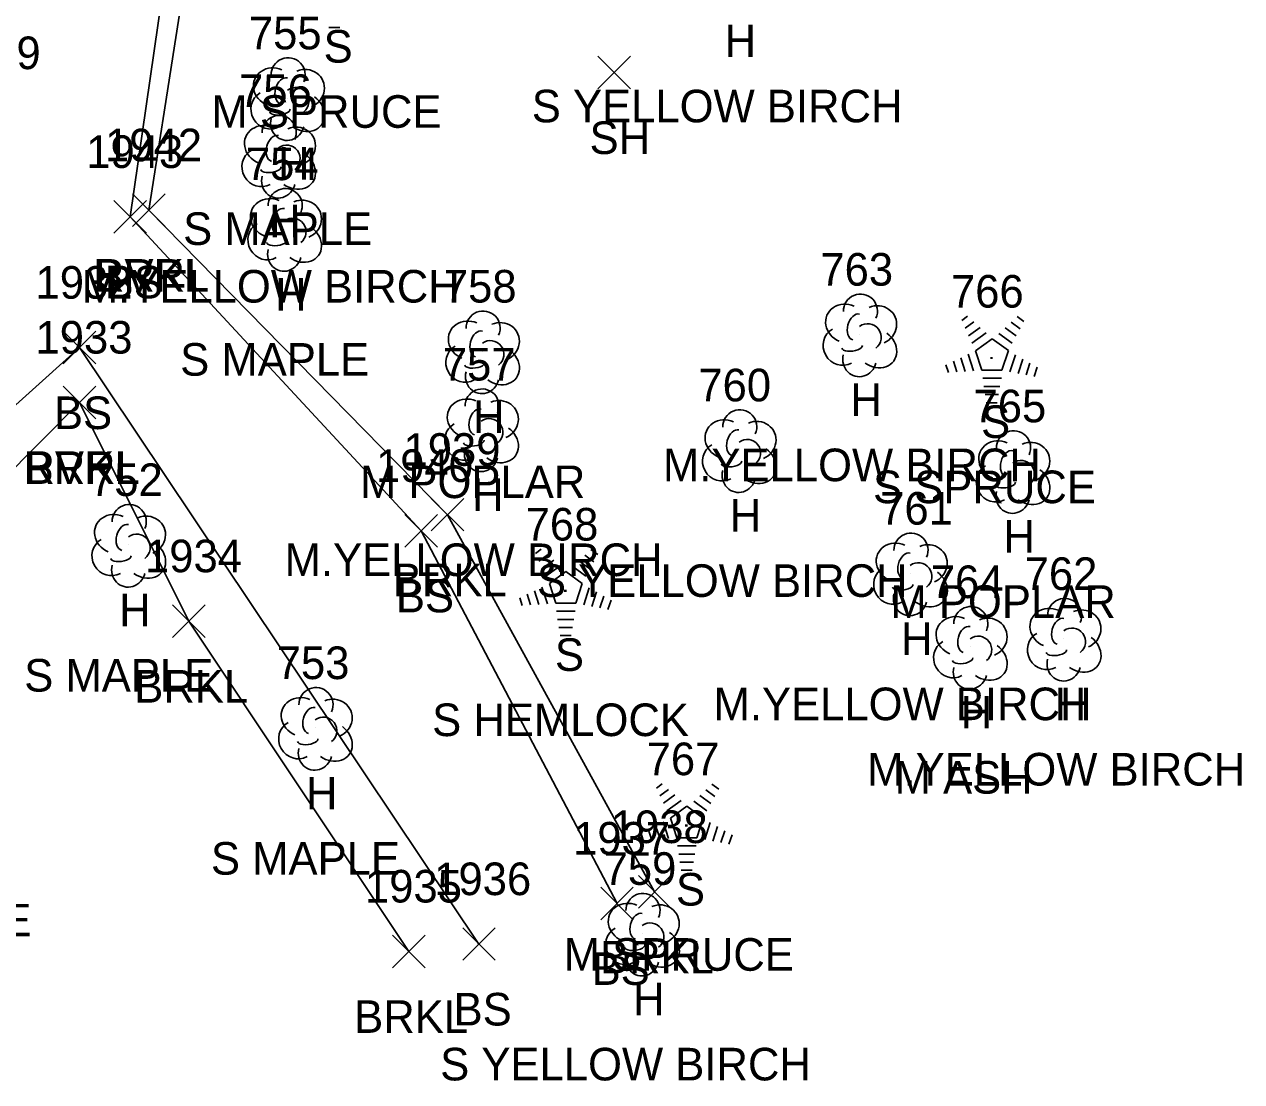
# Model space of a CAD drawing. Extents: x 1545627 to 1546562, y 571176 to 576667.
# Drawn here: x 1546286.7 to 1546361.4, y 572282.6 to 572347.5 of the extents above; entities that cross this region are included whole.
import ezdxf

# ---------------------------------------------------------------- set-up
doc = ezdxf.new("R2010")
doc.units = 0
for name, color, linetype in [('L_A', 7, 'Continuous'), ('L_C', 7, 'Continuous'), ('L_I', 7, 'Continuous'), ('L_TIC', 7, 'Continuous'), ('LAWE', 7, 'Continuous'), ('LELB', 7, 'Continuous'), ('LTC', 7, 'Continuous'), ('LTD', 7, 'Continuous')]:
    doc.layers.add(name, color=color, linetype=linetype)

msp = doc.modelspace()

# ---------------------------------------------------------------- linework, layer by layer
at = {"layer": 'L_TIC'}
for points in [[(1546321.87, 572343.496), (1546323.87, 572345.496)], [(1546323.87, 572343.496), (1546321.87, 572345.496)], [(1546292.177, 572334.64), (1546294.177, 572336.64)], [(1546294.177, 572334.64), (1546292.177, 572336.64)], [(1546293.332, 572335.048), (1546295.332, 572337.048)], [(1546295.332, 572335.048), (1546293.332, 572337.048)], [(1546293.332, 572335.048), (1546295.332, 572337.048)], [(1546295.332, 572335.048), (1546293.332, 572337.048)], [(1546289.068, 572326.618), (1546291.068, 572328.618)], [(1546291.068, 572326.618), (1546289.068, 572328.618)], [(1546289.065, 572323.25), (1546291.065, 572325.25)], [(1546291.065, 572323.25), (1546289.065, 572325.25)], [(1546289.065, 572323.25), (1546291.065, 572325.25)], [(1546291.065, 572323.25), (1546289.065, 572325.25)], [(1546311.645, 572316.364), (1546313.645, 572318.364)], [(1546313.645, 572316.364), (1546311.645, 572318.364)], [(1546310.037, 572315.372), (1546312.037, 572317.372)], [(1546312.037, 572315.372), (1546310.037, 572317.372)], [(1546295.785, 572309.832), (1546297.785, 572311.832)], [(1546297.785, 572309.832), (1546295.785, 572311.832)], [(1546324.351, 572293.214), (1546326.351, 572295.214)], [(1546326.351, 572293.214), (1546324.351, 572295.214)], [(1546322.042, 572292.51), (1546324.042, 572294.51)], [(1546324.042, 572292.51), (1546322.042, 572294.51)], [(1546313.576, 572290.02), (1546315.576, 572292.02)], [(1546315.576, 572290.02), (1546313.576, 572292.02)], [(1546309.275, 572289.567), (1546311.275, 572291.567)], [(1546311.275, 572289.567), (1546309.275, 572291.567)]]:
    msp.add_lwpolyline(points, dxfattribs=at)
at = {"layer": 'LAWE'}
for points in [[(1546294.332, 572336.048), (1546297.64, 572357.253), (1546293.462, 572395.876)], [(1546325.351, 572294.214), (1546312.645, 572317.364), (1546294.332, 572336.048)], [(1546121.265, 571957.172), (1546118.803, 571996.677), (1546114.937, 572038.101), (1546108, 572065.636), (1546104.767, 572084.584), (1546111.687, 572095.842), (1546118.703, 572113.935), (1546133.848, 572134.836), (1546145.167, 572135.646), (1546153.927, 572139.019), (1546169.651, 572160.036), (1546189.008, 572163.697), (1546206.714, 572193.958), (1546205.832, 572212.69), (1546216.066, 572227.226), (1546228.024, 572235.176), (1546234.868, 572265.766), (1546262.797, 572295.702), (1546275.487, 572309.557), (1546290.065, 572324.25)], [(1546290.065, 572324.25), (1546296.785, 572310.832), (1546310.275, 572290.567)]]:
    msp.add_lwpolyline(points, dxfattribs=at)
at = {"layer": 'LELB'}
for points in [[(1546323.042, 572293.51), (1546311.037, 572316.372), (1546293.177, 572335.64), (1546296.372, 572357.734)], [(1546138.465, 572142.662), (1546151.843, 572140.861), (1546169.324, 572161.725), (1546185.772, 572170.699), (1546202.895, 572194.936), (1546204.894, 572212.997), (1546215.164, 572227.989), (1546230.472, 572267.575), (1546260.052, 572296.387), (1546273.8, 572312.974), (1546290.068, 572327.618), (1546314.576, 572291.02)]]:
    msp.add_lwpolyline(points, dxfattribs=at)
at = {"layer": 'LTC'}
for p, q in [((1546306.036, 572347.266), (1546305.361, 572347.266)), ((1546344.183, 572329.279), (1546344.538, 572329.537)), ((1546344.393, 572328.814), (1546344.922, 572329.198)), ((1546347.21, 572329.172), (1546347.76, 572328.772)), ((1546347.581, 572329.52), (1546348.001, 572329.215)), ((1546344.602, 572328.348), (1546345.306, 572328.859)), ((1546344.812, 572327.882), (1546345.69, 572328.52)), ((1546346.468, 572328.475), (1546347.278, 572327.886)), ((1546346.839, 572328.823), (1546347.518, 572328.329)), ((1546345.036, 572327.427), (1546346.048, 572328.162)), ((1546346.048, 572328.162), (1546347.045, 572327.437)), ((1546344.126, 572326.992), (1546344.398, 572326.157)), ((1546344.582, 572327.208), (1546344.913, 572326.189)), ((1546345.036, 572327.427), (1546345.423, 572326.234)), ((1546347.045, 572327.437), (1546346.654, 572326.234)), ((1546347.483, 572327.166), (1546347.145, 572326.127)), ((1546347.927, 572326.916), (1546347.64, 572326.031)), ((1546343.216, 572326.559), (1546343.368, 572326.091)), ((1546343.671, 572326.775), (1546343.883, 572326.124)), ((1546346.654, 572326.234), (1546345.423, 572326.234)), ((1546348.372, 572326.666), (1546348.135, 572325.936)), ((1546348.816, 572326.415), (1546348.629, 572325.841)), ((1546346.616, 572325.734), (1546345.471, 572325.734)), ((1546346.532, 572325.234), (1546345.543, 572325.234)), ((1546346.448, 572324.734), (1546345.616, 572324.734)), ((1546346.364, 572324.234), (1546345.689, 572324.234)), ((1546318.04, 572314.986), (1546318.395, 572315.244)), ((1546321.438, 572315.227), (1546321.858, 572314.922)), ((1546318.25, 572314.521), (1546318.779, 572314.905)), ((1546318.459, 572314.055), (1546319.163, 572314.566)), ((1546318.669, 572313.589), (1546319.547, 572314.227)), ((1546320.696, 572314.53), (1546321.375, 572314.036)), ((1546321.067, 572314.878), (1546321.617, 572314.479)), ((1546318.893, 572313.134), (1546319.905, 572313.869)), ((1546319.905, 572313.869), (1546320.902, 572313.144)), ((1546320.325, 572314.182), (1546321.135, 572313.593)), ((1546318.439, 572312.915), (1546318.77, 572311.896)), ((1546318.893, 572313.134), (1546319.28, 572311.941)), ((1546320.902, 572313.144), (1546320.511, 572311.941)), ((1546321.34, 572312.873), (1546321.002, 572311.833)), ((1546317.073, 572312.265), (1546317.225, 572311.798)), ((1546317.528, 572312.482), (1546317.74, 572311.83)), ((1546317.983, 572312.699), (1546318.255, 572311.863)), ((1546321.784, 572312.623), (1546321.497, 572311.738)), ((1546322.229, 572312.373), (1546321.992, 572311.643)), ((1546322.673, 572312.122), (1546322.486, 572311.548)), ((1546320.511, 572311.941), (1546319.28, 572311.941)), ((1546320.473, 572311.441), (1546319.328, 572311.441)), ((1546320.389, 572310.941), (1546319.4, 572310.941)), ((1546320.305, 572310.441), (1546319.473, 572310.441)), ((1546320.221, 572309.941), (1546319.546, 572309.941)), ((1546325.464, 572300.587), (1546325.819, 572300.845)), ((1546328.862, 572300.828), (1546329.281, 572300.523)), ((1546325.674, 572300.122), (1546326.203, 572300.506)), ((1546325.883, 572299.656), (1546326.587, 572300.167)), ((1546328.12, 572300.131), (1546328.799, 572299.637)), ((1546328.491, 572300.48), (1546329.041, 572300.08)), ((1546326.093, 572299.19), (1546326.971, 572299.828)), ((1546326.317, 572298.735), (1546327.329, 572299.47)), ((1546327.329, 572299.47), (1546328.326, 572298.745)), ((1546327.749, 572299.783), (1546328.559, 572299.194)), ((1546326.317, 572298.735), (1546326.704, 572297.542)), ((1546328.326, 572298.745), (1546327.935, 572297.542)), ((1546324.496, 572297.867), (1546324.649, 572297.399)), ((1546324.952, 572298.083), (1546325.164, 572297.432)), ((1546325.407, 572298.3), (1546325.679, 572297.465)), ((1546325.863, 572298.516), (1546326.194, 572297.497)), ((1546328.764, 572298.474), (1546328.426, 572297.435)), ((1546329.208, 572298.224), (1546328.921, 572297.339)), ((1546329.653, 572297.974), (1546329.416, 572297.244)), ((1546327.935, 572297.542), (1546326.704, 572297.542)), ((1546327.896, 572297.042), (1546326.752, 572297.042)), ((1546330.097, 572297.723), (1546329.91, 572297.149)), ((1546327.813, 572296.542), (1546326.824, 572296.542)), ((1546327.729, 572296.042), (1546326.897, 572296.042)), ((1546327.645, 572295.542), (1546326.97, 572295.542))]:
    msp.add_line(p, q, dxfattribs=at)
at = {"layer": 'LTD'}
for p, q in [((1546302.824, 572342.917), (1546302.824, 572342.917)), ((1546302.824, 572342.917), (1546302.824, 572342.917)), ((1546302.275, 572339.379), (1546302.275, 572339.379)), ((1546302.275, 572339.379), (1546302.275, 572339.379)), ((1546302.644, 572334.893), (1546302.644, 572334.893)), ((1546302.644, 572334.893), (1546302.644, 572334.893)), ((1546337.923, 572328.419), (1546337.923, 572328.419)), ((1546337.923, 572328.419), (1546337.923, 572328.419)), ((1546314.781, 572327.382), (1546314.781, 572327.382)), ((1546314.781, 572327.382), (1546314.781, 572327.382)), ((1546314.718, 572322.598), (1546314.718, 572322.598)), ((1546314.718, 572322.598), (1546314.718, 572322.598)), ((1546330.524, 572321.319), (1546330.524, 572321.319)), ((1546330.524, 572321.319), (1546330.524, 572321.319)), ((1546347.314, 572320.033), (1546347.314, 572320.033)), ((1546347.314, 572320.033), (1546347.314, 572320.033)), ((1546293.077, 572315.51), (1546293.077, 572315.51)), ((1546293.077, 572315.51), (1546293.077, 572315.51)), ((1546341.025, 572313.754), (1546341.025, 572313.754)), ((1546341.025, 572313.754), (1546341.025, 572313.754)), ((1546350.453, 572309.746), (1546350.453, 572309.746)), ((1546350.453, 572309.746), (1546350.453, 572309.746)), ((1546344.696, 572309.247), (1546344.696, 572309.247)), ((1546344.696, 572309.247), (1546344.696, 572309.247)), ((1546304.529, 572304.276), (1546304.529, 572304.276)), ((1546304.529, 572304.276), (1546304.529, 572304.276)), ((1546324.59, 572291.65), (1546324.59, 572291.65)), ((1546324.59, 572291.65), (1546324.59, 572291.65))]:
    msp.add_line(p, q, dxfattribs=at)
for centre in [(1546302.871, 572344.351), (1546302.322, 572340.813), (1546302.69, 572336.327), (1546337.97, 572329.853), (1546314.828, 572328.816), (1546314.765, 572324.032), (1546330.571, 572322.753), (1546347.361, 572321.467), (1546293.124, 572316.944), (1546341.071, 572315.188), (1546350.5, 572311.18), (1546344.743, 572310.681), (1546304.576, 572305.71), (1546324.636, 572293.084)]:
    msp.add_arc(centre, 1.047, 335.52715, 180.95627, dxfattribs=at)
for centre, major_axis, ratio, start_param, end_param in [((1546302.033, 572343.584), (1.21, -0.512), 0.895232, 1.570796, 4.712389), ((1546303.866, 572343.501), (-1.141, -0.483), 0.949671, 1.570796, 4.712389), ((1546302.616, 572343.376), (-0.208, -0.792), 0.645439, 3.141593, 6.283185), ((1546303.324, 572342.751), (-0.5, 0.667), 0.989748, 3.141593, 6.283185), ((1546301.741, 572342.209), (0.584, -1.042), 0.959034, 3.141593, 6.283185), ((1546303.825, 572342.084), (-1.09, 0.792), 0.841452, 1.570796, 4.712389), ((1546302.366, 572342.167), (-0.625, -0.083), 0.423636, 0, 3.141593), ((1546301.483, 572340.046), (1.21, -0.512), 0.895232, 1.570796, 4.712389), ((1546302.825, 572341.417), (0.265, 1.061), 0.942809, 1.570796, 4.712389), ((1546303.316, 572339.963), (-1.141, -0.483), 0.949671, 1.570796, 4.712389), ((1546302.066, 572339.838), (-0.208, -0.792), 0.645439, 3.141593, 6.283185), ((1546301.192, 572338.671), (0.584, -1.042), 0.959034, 3.141593, 6.283185), ((1546302.775, 572339.213), (-0.5, 0.667), 0.989748, 3.141593, 6.283185), ((1546303.275, 572338.546), (-1.09, 0.792), 0.841452, 1.570796, 4.712389), ((1546302.275, 572337.879), (0.265, 1.061), 0.942809, 1.570796, 4.712389), ((1546301.817, 572338.629), (-0.625, -0.083), 0.423636, 0, 3.141593), ((1546301.852, 572335.56), (1.21, -0.512), 0.895232, 1.570796, 4.712389), ((1546303.685, 572335.477), (-1.141, -0.483), 0.949671, 1.570796, 4.712389), ((1546302.435, 572335.351), (-0.208, -0.792), 0.645439, 3.141593, 6.283185), ((1546301.56, 572334.185), (0.584, -1.042), 0.959034, 3.141593, 6.283185), ((1546303.144, 572334.726), (-0.5, 0.667), 0.989748, 3.141593, 6.283185), ((1546303.644, 572334.06), (-1.09, 0.792), 0.841452, 1.570796, 4.712389), ((1546302.644, 572333.393), (0.265, 1.061), 0.942809, 1.570796, 4.712389), ((1546302.185, 572334.143), (-0.625, -0.083), 0.423636, 0, 3.141593), ((1546337.131, 572329.086), (1.21, -0.512), 0.895232, 1.570796, 4.712389), ((1546338.964, 572329.003), (-1.141, -0.483), 0.949671, 1.570796, 4.712389), ((1546313.99, 572328.048), (1.21, -0.512), 0.895232, 1.570796, 4.712389), ((1546315.823, 572327.965), (-1.141, -0.483), 0.949671, 1.570796, 4.712389), ((1546337.714, 572328.878), (-0.208, -0.792), 0.645439, 3.141593, 6.283185), ((1546338.423, 572328.253), (-0.5, 0.667), 0.989748, 3.141593, 6.283185), ((1546314.573, 572327.84), (-0.208, -0.792), 0.645439, 3.141593, 6.283185), ((1546336.84, 572327.711), (0.584, -1.042), 0.959034, 3.141593, 6.283185), ((1546338.923, 572327.586), (-1.09, 0.792), 0.841452, 1.570796, 4.712389), ((1546313.698, 572326.673), (0.584, -1.042), 0.959034, 3.141593, 6.283185), ((1546315.281, 572327.215), (-0.5, 0.667), 0.989748, 3.141593, 6.283185), ((1546337.465, 572327.669), (-0.625, -0.083), 0.423636, 0, 3.141593), ((1546315.781, 572326.549), (-1.09, 0.792), 0.841452, 1.570796, 4.712389), ((1546337.923, 572326.919), (0.265, 1.061), 0.942809, 1.570796, 4.712389), ((1546314.323, 572326.632), (-0.625, -0.083), 0.423636, 0, 3.141593), ((1546314.782, 572325.882), (0.265, 1.061), 0.942809, 1.570796, 4.712389), ((1546313.927, 572323.265), (1.21, -0.512), 0.895232, 1.570796, 4.712389), ((1546314.51, 572323.057), (-0.208, -0.792), 0.645439, 3.141593, 6.283185), ((1546315.76, 572323.182), (-1.141, -0.483), 0.949671, 1.570796, 4.712389), ((1546315.218, 572322.432), (-0.5, 0.667), 0.989748, 3.141593, 6.283185), ((1546329.732, 572321.986), (1.21, -0.512), 0.895232, 1.570796, 4.712389), ((1546331.565, 572321.903), (-1.141, -0.483), 0.949671, 1.570796, 4.712389), ((1546313.635, 572321.89), (0.584, -1.042), 0.959034, 3.141593, 6.283185), ((1546315.719, 572321.765), (-1.09, 0.792), 0.841452, 1.570796, 4.712389), ((1546330.315, 572321.777), (-0.208, -0.792), 0.645439, 3.141593, 6.283185), ((1546314.26, 572321.848), (-0.625, -0.083), 0.423636, 0, 3.141593), ((1546331.024, 572321.153), (-0.5, 0.667), 0.989748, 3.141593, 6.283185), ((1546346.523, 572320.7), (1.21, -0.512), 0.895232, 1.570796, 4.712389), ((1546348.356, 572320.617), (-1.141, -0.483), 0.949671, 1.570796, 4.712389), ((1546314.719, 572321.098), (0.265, 1.061), 0.942809, 1.570796, 4.712389), ((1546329.441, 572320.611), (0.584, -1.042), 0.959034, 3.141593, 6.283185), ((1546331.524, 572320.486), (-1.09, 0.792), 0.841452, 1.570796, 4.712389), ((1546347.106, 572320.492), (-0.208, -0.792), 0.645439, 3.141593, 6.283185), ((1546330.066, 572320.569), (-0.625, -0.083), 0.423636, 0, 3.141593), ((1546346.231, 572319.325), (0.584, -1.042), 0.959034, 3.141593, 6.283185), ((1546347.815, 572319.867), (-0.5, 0.667), 0.989748, 3.141593, 6.283185), ((1546330.524, 572319.819), (0.265, 1.061), 0.942809, 1.570796, 4.712389), ((1546348.315, 572319.2), (-1.09, 0.792), 0.841452, 1.570796, 4.712389), ((1546347.315, 572318.533), (0.265, 1.061), 0.942809, 1.570796, 4.712389), ((1546346.856, 572319.283), (-0.625, -0.083), 0.423636, 0, 3.141593), ((1546292.285, 572316.176), (1.21, -0.512), 0.895232, 1.570796, 4.712389), ((1546294.118, 572316.093), (-1.141, -0.483), 0.949671, 1.570796, 4.712389), ((1546292.868, 572315.968), (-0.208, -0.792), 0.645439, 3.141593, 6.283185), ((1546291.994, 572314.801), (0.584, -1.042), 0.959034, 3.141593, 6.283185), ((1546293.577, 572315.343), (-0.5, 0.667), 0.989748, 3.141593, 6.283185), ((1546340.233, 572314.42), (1.21, -0.512), 0.895232, 1.570796, 4.712389), ((1546294.077, 572314.677), (-1.09, 0.792), 0.841452, 1.570796, 4.712389), ((1546340.816, 572314.212), (-0.208, -0.792), 0.645439, 3.141593, 6.283185), ((1546342.066, 572314.337), (-1.141, -0.483), 0.949671, 1.570796, 4.712389), ((1546293.077, 572314.01), (0.265, 1.061), 0.942809, 1.570796, 4.712389), ((1546292.619, 572314.76), (-0.625, -0.083), 0.423636, 0, 3.141593), ((1546341.525, 572313.587), (-0.5, 0.667), 0.989748, 3.141593, 6.283185), ((1546339.941, 572313.045), (0.584, -1.042), 0.959034, 3.141593, 6.283185), ((1546342.025, 572312.921), (-1.09, 0.792), 0.841452, 1.570796, 4.712389), ((1546340.566, 572313.004), (-0.625, -0.083), 0.423636, 0, 3.141593), ((1546341.025, 572312.254), (0.265, 1.061), 0.942809, 1.570796, 4.712389), ((1546343.905, 572309.913), (1.21, -0.512), 0.895232, 1.570796, 4.712389), ((1546349.661, 572310.413), (1.21, -0.512), 0.895232, 1.570796, 4.712389), ((1546351.494, 572310.33), (-1.141, -0.483), 0.949671, 1.570796, 4.712389), ((1546344.488, 572309.705), (-0.208, -0.792), 0.645439, 3.141593, 6.283185), ((1546345.738, 572309.83), (-1.141, -0.483), 0.949671, 1.570796, 4.712389), ((1546350.244, 572310.204), (-0.208, -0.792), 0.645439, 3.141593, 6.283185), ((1546350.953, 572309.579), (-0.5, 0.667), 0.989748, 3.141593, 6.283185), ((1546345.197, 572309.08), (-0.5, 0.667), 0.989748, 3.141593, 6.283185), ((1546349.37, 572309.038), (0.584, -1.042), 0.959034, 3.141593, 6.283185), ((1546351.453, 572308.913), (-1.09, 0.792), 0.841452, 1.570796, 4.712389), ((1546343.613, 572308.538), (0.584, -1.042), 0.959034, 3.141593, 6.283185), ((1546345.697, 572308.414), (-1.09, 0.792), 0.841452, 1.570796, 4.712389), ((1546349.995, 572308.996), (-0.625, -0.083), 0.423636, 0, 3.141593), ((1546344.238, 572308.497), (-0.625, -0.083), 0.423636, 0, 3.141593), ((1546350.453, 572308.246), (0.265, 1.061), 0.942809, 1.570796, 4.712389), ((1546344.697, 572307.747), (0.265, 1.061), 0.942809, 1.570796, 4.712389), ((1546303.737, 572304.942), (1.21, -0.512), 0.895232, 1.570796, 4.712389), ((1546305.57, 572304.859), (-1.141, -0.483), 0.949671, 1.570796, 4.712389), ((1546304.32, 572304.734), (-0.208, -0.792), 0.645439, 3.141593, 6.283185), ((1546303.446, 572303.567), (0.584, -1.042), 0.959034, 3.141593, 6.283185), ((1546305.029, 572304.109), (-0.5, 0.667), 0.989748, 3.141593, 6.283185), ((1546305.529, 572303.443), (-1.09, 0.792), 0.841452, 1.570796, 4.712389), ((1546304.529, 572302.776), (0.265, 1.061), 0.942809, 1.570796, 4.712389), ((1546304.071, 572303.526), (-0.625, -0.083), 0.423636, 0, 3.141593), ((1546323.798, 572292.317), (1.21, -0.512), 0.895232, 1.570796, 4.712389), ((1546325.631, 572292.234), (-1.141, -0.483), 0.949671, 1.570796, 4.712389), ((1546324.381, 572292.109), (-0.208, -0.792), 0.645439, 3.141593, 6.283185), ((1546323.506, 572290.942), (0.584, -1.042), 0.959034, 3.141593, 6.283185), ((1546325.09, 572291.484), (-0.5, 0.667), 0.989748, 3.141593, 6.283185), ((1546325.59, 572290.817), (-1.09, 0.792), 0.841452, 1.570796, 4.712389), ((1546324.59, 572290.15), (0.265, 1.061), 0.942809, 1.570796, 4.712389), ((1546324.131, 572290.9), (-0.625, -0.083), 0.423636, 0, 3.141593)]:
    msp.add_ellipse(centre, major_axis=major_axis, ratio=ratio, start_param=start_param, end_param=end_param, dxfattribs=at)

# ---------------------------------------------------------------- texts
at = {"layer": 'L_A'}
for s, p in [('S', (1546305.045, 572345.104)), ('H', (1546329.641, 572345.439)), ('SH', (1546321.358, 572339.496)), ('H', (1546302.258, 572337.917)), ('H', (1546301.708, 572334.379)), ('RVRL', (1546290.899, 572331.048)), ('BRKL', (1546290.978, 572331.048)), ('BS', (1546291.618, 572330.64)), ('H', (1546302.077, 572329.893)), ('H', (1546337.356, 572323.419)), ('BS', (1546288.509, 572322.618)), ('H', (1546314.214, 572322.382)), ('S', (1546345.374, 572322.071)), ('RVRL', (1546286.632, 572319.25)), ('BRKL', (1546286.711, 572319.25)), ('H', (1546314.152, 572317.598)), ('H', (1546329.957, 572316.319)), ('H', (1546346.748, 572315.033)), ('BRKL', (1546309.29, 572312.364)), ('BS', (1546309.478, 572311.372)), ('H', (1546292.51, 572310.51)), ('H', (1546340.458, 572308.754)), ('S', (1546319.231, 572307.778)), ('BRKL', (1546293.431, 572305.832)), ('H', (1546349.886, 572304.746)), ('H', (1546344.13, 572304.247)), ('H', (1546303.962, 572299.276)), ('S', (1546326.655, 572293.379)), ('BRKL', (1546321.996, 572289.214)), ('BS', (1546321.483, 572288.51)), ('H', (1546324.023, 572286.65)), ('BRKL', (1546306.921, 572285.567)), ('BS', (1546313.017, 572286.02))]:
    msp.add_text(s, height=2, dxfattribs=at).set_placement(p)
at = {"layer": 'L_C'}
for s, p in [('S YELLOW BIRCH', (1546317.814, 572341.439)), ('M SPRUCE', (1546298.164, 572341.104)), ('S MAPLE', (1546296.431, 572333.917)), ('M.YELLOW BIRCH', (1546290.212, 572330.379)), ('S MAPLE', (1546296.25, 572325.893)), ('M.YELLOW BIRCH', (1546325.86, 572319.419)), ('M POPLAR', (1546307.277, 572318.382)), ('S SPRUCE', (1546338.744, 572318.071)), ('M.YELLOW BIRCH', (1546302.655, 572313.598)), ('S YELLOW BIRCH', (1546318.13, 572312.319)), ('M POPLAR', (1546339.811, 572311.033)), ('S MAPLE', (1546286.683, 572306.51)), ('M.YELLOW BIRCH', (1546328.962, 572304.754)), ('S HEMLOCK', (1546311.703, 572303.778)), ('M.YELLOW BIRCH', (1546338.39, 572300.746)), ('M ASH', (1546340.067, 572300.247)), ('S MAPLE', (1546298.135, 572295.276)), ('S MAPLE', (1546275.528, 572291.485)), ('M SPRUCE', (1546319.773, 572289.379)), ('S YELLOW BIRCH', (1546312.196, 572282.65))]:
    msp.add_text(s, height=2, dxfattribs=at).set_placement(p)
at = {"layer": 'L_I'}
for s, p in [('755', (1546300.462, 572345.917)), ('1929', (1546281.742, 572344.705)), ('756', (1546299.857, 572342.379)), ('1942', (1546291.639, 572339.048)), ('1942', (1546291.639, 572339.048)), ('1943', (1546290.484, 572338.64)), ('754', (1546300.281, 572337.893)), ('763', (1546335.513, 572331.419)), ('1932', (1546287.375, 572330.618)), ('758', (1546312.419, 572330.382)), ('766', (1546343.523, 572330.071)), ('1933', (1546287.372, 572327.25)), ('1933', (1546287.372, 572327.25)), ('757', (1546312.356, 572325.598)), ('760', (1546328.028, 572324.319)), ('765', (1546344.905, 572323.033)), ('1939', (1546309.944, 572320.364)), ('1940', (1546308.258, 572319.372)), ('752', (1546290.715, 572318.51)), ('761', (1546339.182, 572316.754)), ('768', (1546317.435, 572315.778)), ('1934', (1546294.092, 572313.832)), ('764', (1546342.287, 572312.247)), ('762', (1546348.043, 572312.746)), ('753', (1546302.167, 572307.276)), ('767', (1546324.859, 572301.379)), ('1937', (1546320.349, 572296.51)), ('1938', (1546322.658, 572297.214)), ('759', (1546322.219, 572294.65)), ('1935', (1546307.582, 572293.567)), ('1936', (1546311.828, 572294.02))]:
    msp.add_text(s, height=2, dxfattribs=at).set_placement(p)
at = {"layer": 'LTC'}
for p in [(1546345.931, 572327.175), (1546319.788, 572312.882), (1546327.211, 572298.483)]:
    msp.add_text('.', height=1.037, rotation=270, dxfattribs=at).set_placement(p)

doc.saveas('drawing.dxf')
